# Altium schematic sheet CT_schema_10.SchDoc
size 274 x 160 mm
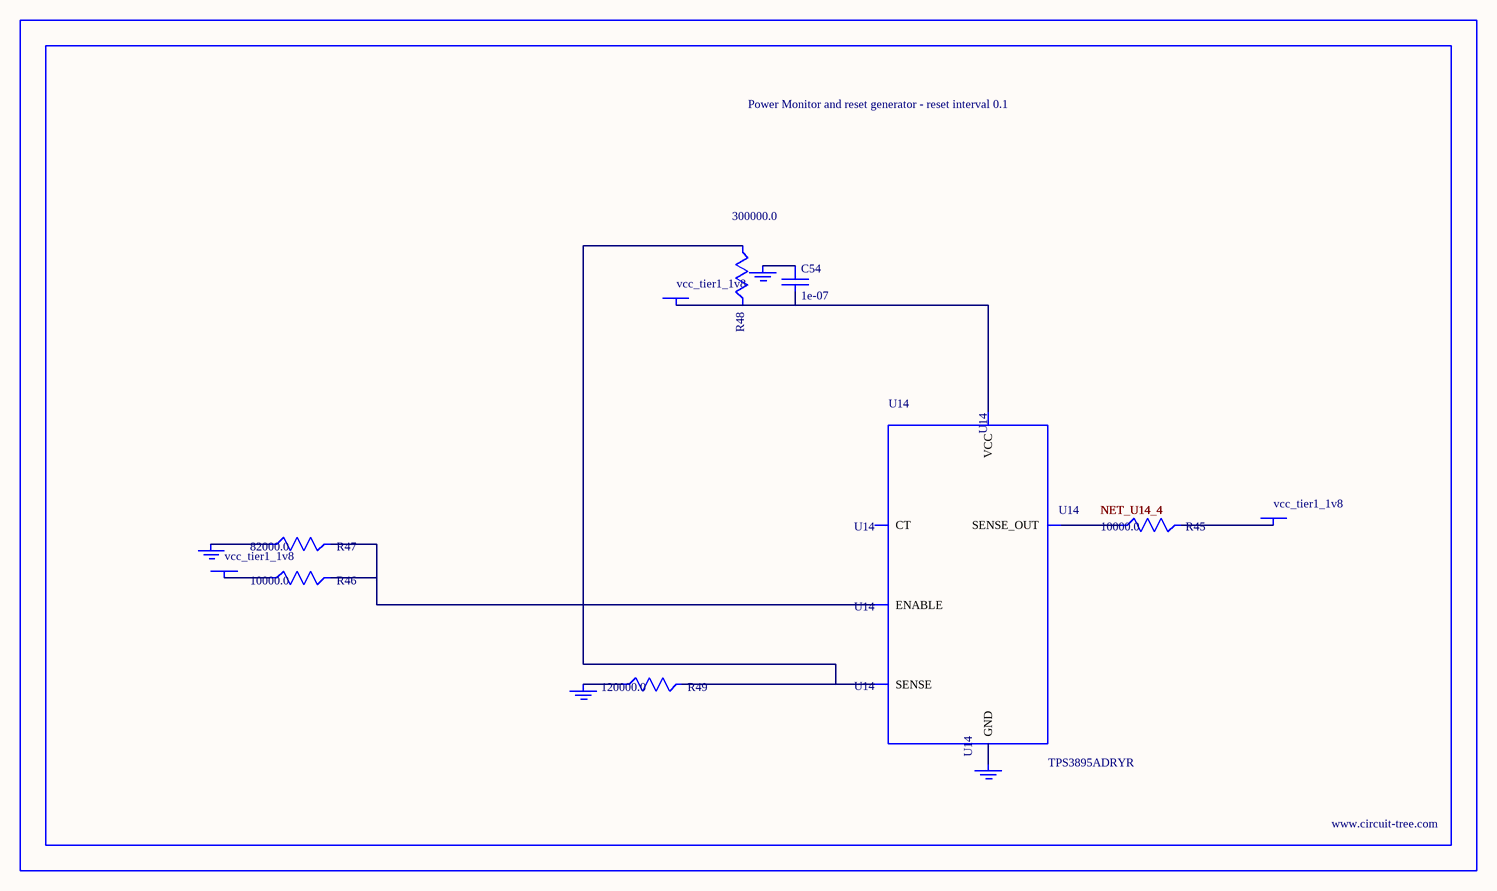
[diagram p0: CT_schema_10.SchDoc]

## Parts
BORDER9  (no value)
C54  1e-07  [C0402]
GND_INSTANCE_9_0  (no value)
GND_INSTANCE_9_1  (no value)
GND_INSTANCE_9_2  (no value)
GND_INSTANCE_9_3  (no value)
POWER_INSTANCE_9_0  vcc_tier1_1v8
POWER_INSTANCE_9_1  vcc_tier1_1v8
POWER_INSTANCE_9_2  vcc_tier1_1v8
R45  10000.0  [R0603]
R46  10000.0  [R0603]
R47  82000.0  [R0603]
R48  300000.0  [R0603]
R49  120000.0  [R0603]
U14  TPS3895ADRYR  [SON-6]

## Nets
NetC54_1: C54.1 GND_INSTANCE_9_2.0(GND)
NetC54_2: C54.2 POWER_INSTANCE_9_2.0(PWR) R48.2 U14.6(VCC)
NetGND_INSTANCE_9_0_0: GND_INSTANCE_9_0.0(GND) R47.1
NetGND_INSTANCE_9_1_0: GND_INSTANCE_9_1.0(GND) R49.1
NetGND_INSTANCE_9_3_0: GND_INSTANCE_9_3.0(GND) U14.2(GND)
NetPOWER_INSTANCE_9_0_0: POWER_INSTANCE_9_0.0(PWR) R46.1
NetPOWER_INSTANCE_9_1_0: POWER_INSTANCE_9_1.0(PWR) R45.2
NetR45_1: R45.1 U14.4(SENSE_OUT)
NetR46_2: R46.2 R47.2 U14.1(ENABLE)
NetR48_1: R48.1 R49.2 U14.3(SENSE)

Not connected (* = marked no-connect by the designer): U14 5(CT)

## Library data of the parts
BORDER9 = BORDER_PAGE9
C54 = C0402C104K3RACTU
GND_INSTANCE_9_0-GND_INSTANCE_9_3 = GND
POWER_INSTANCE_9_0-POWER_INSTANCE_9_2 = PWR
R45 R46 = RC0603JR-0710KL
R47 = RC0603JR-0782KL
R48 = RC0603JR-07300KL
R49 = RC0603JR-07120KL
